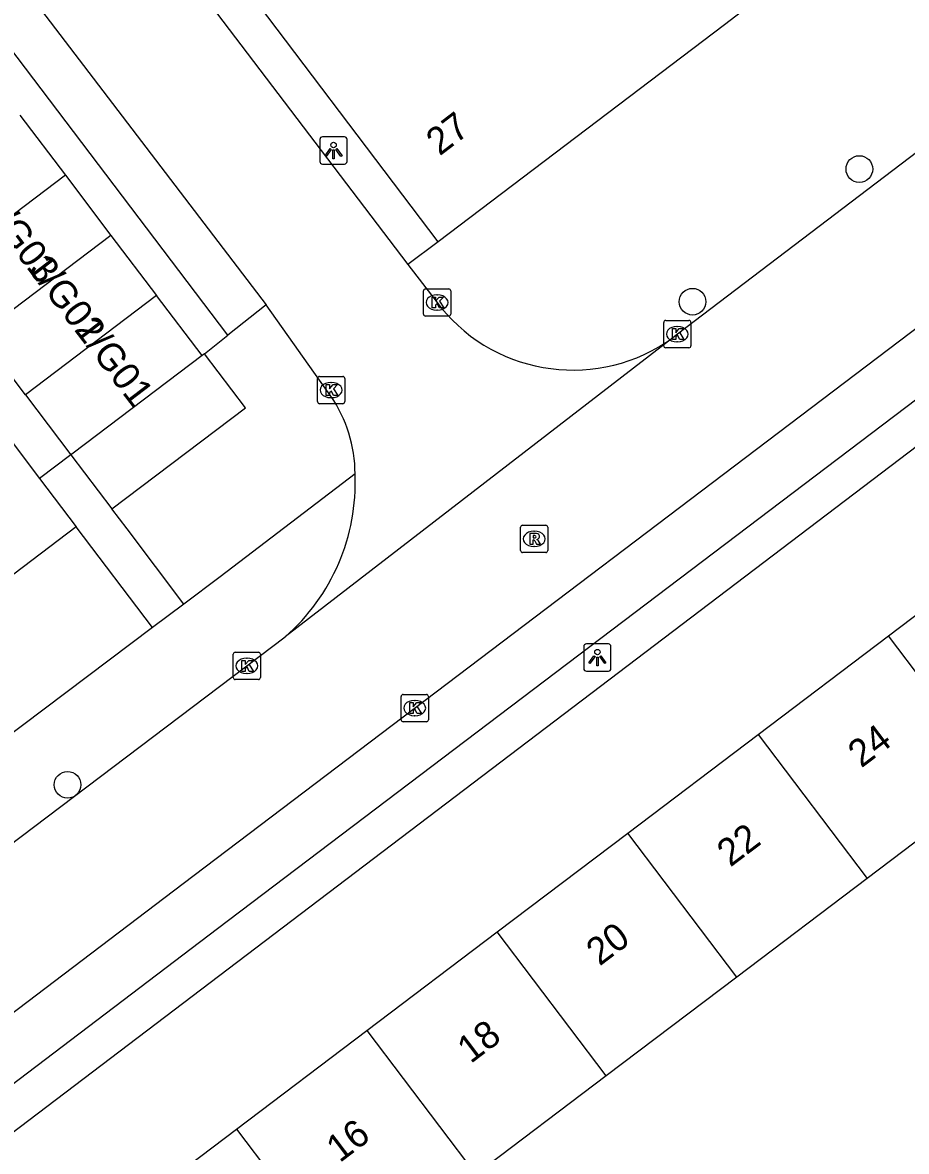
# Model space of a CAD drawing. Extents: x 160037 to 160839, y 385326 to 386441.
# Drawn here: x 160285.29 to 160317.7, y 385893.36 to 385934.78 of the extents above; entities that cross this region are included whole.
import ezdxf

# ---------------------------------------------------------------- set-up
doc = ezdxf.new("R2010")
doc.units = 0
for name, color, linetype in [('IMGEO_Boom', 7, 'Continuous'), ('IMGEO_Groenvoorziening', 7, 'Continuous'), ('IMGEO_Kolk', 7, 'Continuous'), ('IMGEO_Lage_trafo', 7, 'Continuous'), ('IMGEO_Lichtpunt', 7, 'Continuous'), ('IMGEO_Pand', 7, 'Continuous'), ('IMGEO_Pand_nummerreeks', 7, 'Continuous'), ('IMGEO_Rijbaan_lokaal_open', 7, 'Continuous'), ('IMGEO_Rioolput', 7, 'Continuous'), ('IMGEO_Voetpad_open', 7, 'Continuous')]:
    doc.layers.add(name, color=color, linetype=linetype)

msp = doc.modelspace()

# ---------------------------------------------------------------- linework, layer by layer
at = {"layer": 'IMGEO_Boom'}
for centre in [(160315.976, 385929.404), (160309.859, 385924.538), (160286.944, 385906.816)]:
    msp.add_circle(centre, 0.489, dxfattribs=at)
at = {"layer": 'IMGEO_Groenvoorziening'}
msp.add_lwpolyline([(160291.96, 385922.629), (160292.815, 385923.307)], dxfattribs=at)
at = {"layer": 'IMGEO_Kolk'}
for p, q in [((160299.993, 385924.082), (160299.993, 385924.934)), ((160300.068, 385925.008), (160300.92, 385925.008)), ((160300.481, 385924.788), (160300.506, 385924.788)), ((160300.994, 385924.934), (160300.994, 385924.082)), ((160300.92, 385924.008), (160300.068, 385924.008)), ((160300.504, 385924.228), (160300.479, 385924.228)), ((160308.801, 385922.923), (160308.801, 385923.775)), ((160308.876, 385923.849), (160309.728, 385923.849)), ((160309.289, 385923.629), (160309.314, 385923.629)), ((160309.802, 385923.775), (160309.802, 385922.923)), ((160309.728, 385922.849), (160308.876, 385922.849)), ((160309.312, 385923.069), (160309.287, 385923.069)), ((160296.107, 385920.871), (160296.107, 385921.723)), ((160296.182, 385921.797), (160297.034, 385921.797)), ((160296.595, 385921.577), (160296.62, 385921.577)), ((160297.108, 385921.723), (160297.108, 385920.871)), ((160297.034, 385920.797), (160296.182, 385920.797)), ((160296.618, 385921.017), (160296.593, 385921.017)), ((160293.015, 385910.751), (160293.015, 385911.603)), ((160293.09, 385911.677), (160293.942, 385911.677)), ((160294.016, 385911.603), (160294.016, 385910.751)), ((160293.503, 385911.457), (160293.528, 385911.457)), ((160293.942, 385910.677), (160293.09, 385910.677)), ((160293.526, 385910.897), (160293.501, 385910.897)), ((160299.172, 385909.204), (160299.172, 385910.056)), ((160299.247, 385910.13), (160300.099, 385910.13)), ((160299.66, 385909.91), (160299.685, 385909.91)), ((160300.173, 385910.056), (160300.173, 385909.204)), ((160300.099, 385909.13), (160299.247, 385909.13)), ((160299.683, 385909.35), (160299.658, 385909.35))]:
    msp.add_line(p, q, dxfattribs=at)
for points in [[(160299.993, 385924.082), (160299.993, 385924.934)], [(160300.068, 385925.008), (160300.92, 385925.008)], [(160300.994, 385924.934), (160300.994, 385924.082)], [(160300.314, 385924.708), (160300.437, 385924.708), (160300.437, 385924.557), (160300.567, 385924.708), (160300.731, 385924.708), (160300.585, 385924.557), (160300.738, 385924.308), (160300.586, 385924.308), (160300.501, 385924.472), (160300.437, 385924.405), (160300.437, 385924.308), (160300.314, 385924.308), (160300.314, 385924.708)], [(160300.92, 385924.008), (160300.068, 385924.008)], [(160308.801, 385922.923), (160308.801, 385923.775)], [(160308.876, 385923.849), (160309.728, 385923.849)], [(160309.122, 385923.549), (160309.245, 385923.549), (160309.245, 385923.398), (160309.375, 385923.549), (160309.539, 385923.549), (160309.393, 385923.398), (160309.546, 385923.149), (160309.394, 385923.149), (160309.309, 385923.313), (160309.245, 385923.246), (160309.245, 385923.149), (160309.122, 385923.149), (160309.122, 385923.549)], [(160309.802, 385923.775), (160309.802, 385922.923)], [(160309.728, 385922.849), (160308.876, 385922.849)], [(160296.107, 385920.871), (160296.107, 385921.723)], [(160296.182, 385921.797), (160297.034, 385921.797)], [(160296.428, 385921.497), (160296.551, 385921.497), (160296.551, 385921.346), (160296.681, 385921.497), (160296.845, 385921.497), (160296.699, 385921.346), (160296.852, 385921.097), (160296.7, 385921.097), (160296.615, 385921.261), (160296.551, 385921.194), (160296.551, 385921.097), (160296.428, 385921.097), (160296.428, 385921.497)], [(160297.108, 385921.723), (160297.108, 385920.871)], [(160297.034, 385920.797), (160296.182, 385920.797)], [(160293.015, 385910.751), (160293.015, 385911.603)], [(160293.09, 385911.677), (160293.942, 385911.677)], [(160294.016, 385911.603), (160294.016, 385910.751)], [(160293.336, 385911.377), (160293.459, 385911.377), (160293.459, 385911.226), (160293.589, 385911.377), (160293.753, 385911.377), (160293.607, 385911.226), (160293.76, 385910.977), (160293.608, 385910.977), (160293.523, 385911.141), (160293.459, 385911.074), (160293.459, 385910.977), (160293.336, 385910.977), (160293.336, 385911.377)], [(160293.942, 385910.677), (160293.09, 385910.677)], [(160299.172, 385909.204), (160299.172, 385910.056)], [(160299.247, 385910.13), (160300.099, 385910.13)], [(160300.173, 385910.056), (160300.173, 385909.204)], [(160299.493, 385909.83), (160299.616, 385909.83), (160299.616, 385909.679), (160299.746, 385909.83), (160299.91, 385909.83), (160299.764, 385909.679), (160299.917, 385909.43), (160299.765, 385909.43), (160299.68, 385909.594), (160299.616, 385909.527), (160299.616, 385909.43), (160299.493, 385909.43), (160299.493, 385909.83)], [(160300.099, 385909.13), (160299.247, 385909.13)]]:
    msp.add_lwpolyline(points, dxfattribs=at)
for centre, start, end in [((160300.07, 385924.932), 91.552, 178.448), ((160300.07, 385924.932), 91.552, 178.448), ((160300.918, 385924.932), 1.552, 88.448), ((160300.918, 385924.932), 1.552, 88.448), ((160300.07, 385924.084), 181.552, 268.448), ((160300.07, 385924.084), 181.552, 268.448), ((160300.918, 385924.084), 271.552, 358.448), ((160300.918, 385924.084), 271.552, 358.448), ((160308.878, 385923.773), 91.552, 178.448), ((160308.878, 385923.773), 91.552, 178.448), ((160309.726, 385923.773), 1.552, 88.448), ((160309.726, 385923.773), 1.552, 88.448), ((160308.878, 385922.925), 181.552, 268.448), ((160308.878, 385922.925), 181.552, 268.448), ((160309.726, 385922.925), 271.552, 358.448), ((160309.726, 385922.925), 271.552, 358.448), ((160296.184, 385921.721), 91.552, 178.448), ((160296.184, 385921.721), 91.552, 178.448), ((160297.032, 385921.721), 1.552, 88.448), ((160297.032, 385921.721), 1.552, 88.448), ((160296.184, 385920.873), 181.552, 268.448), ((160296.184, 385920.873), 181.552, 268.448), ((160297.032, 385920.873), 271.552, 358.448), ((160297.032, 385920.873), 271.552, 358.448), ((160293.092, 385911.601), 91.552, 178.448), ((160293.092, 385911.601), 91.552, 178.448), ((160293.94, 385911.601), 1.552, 88.448), ((160293.94, 385911.601), 1.552, 88.448), ((160293.092, 385910.753), 181.552, 268.448), ((160293.092, 385910.753), 181.552, 268.448), ((160293.94, 385910.753), 271.552, 358.448), ((160293.94, 385910.753), 271.552, 358.448), ((160299.249, 385910.054), 91.552, 178.448), ((160299.249, 385910.054), 91.552, 178.448), ((160300.097, 385910.054), 1.552, 88.448), ((160300.097, 385910.054), 1.552, 88.448), ((160299.249, 385909.206), 181.552, 268.448), ((160299.249, 385909.206), 181.552, 268.448), ((160300.097, 385909.206), 271.552, 358.448), ((160300.097, 385909.206), 271.552, 358.448)]:
    msp.add_arc(centre, 0.0765, start, end, dxfattribs=at)
for centre, major_axis, ratio, start_param, end_param in [((160300.48, 385924.508), (-0.387, 0.002), 0.722429, 4.712389, 7.853982), ((160300.505, 385924.508), (-0.39, 0.002), 0.717154, 1.570796, 4.712389), ((160309.288, 385923.349), (-0.387, 0.002), 0.722429, 4.712389, 7.853982), ((160309.313, 385923.349), (-0.39, 0.002), 0.717154, 1.570796, 4.712389), ((160296.594, 385921.297), (-0.387, 0.002), 0.722429, 4.712389, 7.853982), ((160296.619, 385921.297), (-0.39, 0.002), 0.717154, 1.570796, 4.712389), ((160293.502, 385911.177), (-0.387, 0.002), 0.722429, 4.712389, 7.853982), ((160293.527, 385911.177), (-0.39, 0.002), 0.717154, 1.570796, 4.712389), ((160299.659, 385909.63), (-0.387, 0.002), 0.722429, 4.712389, 7.853982), ((160299.684, 385909.63), (-0.39, 0.002), 0.717154, 1.570796, 4.712389)]:
    msp.add_ellipse(centre, major_axis=major_axis, ratio=ratio, start_param=start_param, end_param=end_param, dxfattribs=at)
at = {"layer": 'IMGEO_Lage_trafo'}
for points in [[(160288.567, 385916.938), (160293.467, 385920.64), (160291.96, 385922.629)], [(160291.96, 385922.629), (160291.873, 385922.56)], [(160287.066, 385918.921), (160288.567, 385916.938)]]:
    msp.add_lwpolyline(points, dxfattribs=at)
at = {"layer": 'IMGEO_Lichtpunt'}
for p, q in [((160297.098, 385930.584), (160296.29, 385930.584)), ((160297.098, 385930.584), (160296.29, 385930.584)), ((160296.196, 385930.489), (160296.196, 385929.682)), ((160296.196, 385930.489), (160296.196, 385929.682)), ((160297.192, 385929.682), (160297.192, 385930.489)), ((160297.192, 385929.682), (160297.192, 385930.489)), ((160296.29, 385929.588), (160297.098, 385929.588)), ((160296.29, 385929.588), (160297.098, 385929.588)), ((160306.774, 385911.982), (160305.966, 385911.982)), ((160306.774, 385911.982), (160305.966, 385911.982)), ((160305.872, 385911.887), (160305.872, 385911.08)), ((160305.872, 385911.887), (160305.872, 385911.08)), ((160306.868, 385911.08), (160306.868, 385911.887)), ((160306.868, 385911.08), (160306.868, 385911.887)), ((160305.966, 385910.986), (160306.774, 385910.986)), ((160305.966, 385910.986), (160306.774, 385910.986))]:
    msp.add_line(p, q, dxfattribs=at)
for points in [[(160296.57, 385930.153), (160296.609, 385930.125), (160296.421, 385929.863), (160296.383, 385929.89), (160296.57, 385930.153)], [(160296.782, 385930.125), (160296.82, 385930.152), (160297.007, 385929.89), (160296.968, 385929.862), (160296.782, 385930.125)], [(160296.672, 385930.105), (160296.719, 385930.105), (160296.719, 385929.783), (160296.672, 385929.783), (160296.672, 385930.105)], [(160306.246, 385911.551), (160306.285, 385911.523), (160306.097, 385911.261), (160306.059, 385911.288), (160306.246, 385911.551)], [(160306.348, 385911.503), (160306.395, 385911.503), (160306.395, 385911.181), (160306.348, 385911.181), (160306.348, 385911.503)], [(160306.458, 385911.523), (160306.496, 385911.55), (160306.683, 385911.288), (160306.644, 385911.26), (160306.458, 385911.523)]]:
    msp.add_lwpolyline(points, dxfattribs=at)
for centre in [(160296.695, 385930.287), (160306.371, 385911.685)]:
    msp.add_circle(centre, 0.0994, dxfattribs=at)
for centre, start, end in [((160296.29, 385930.489), 90, 180), ((160296.29, 385930.489), 90, 180), ((160297.098, 385930.489), 0, 90), ((160297.098, 385930.489), 0, 90), ((160296.29, 385929.682), 180, 270), ((160296.29, 385929.682), 180, 270), ((160297.098, 385929.682), 270, 0), ((160297.098, 385929.682), 270, 360), ((160305.966, 385911.887), 90, 180), ((160305.966, 385911.887), 90, 180), ((160306.774, 385911.887), 0, 90), ((160306.774, 385911.887), 0, 90), ((160305.966, 385911.08), 180, 270), ((160305.966, 385911.08), 180, 270), ((160306.774, 385911.08), 270, 0), ((160306.774, 385911.08), 270, 360)]:
    msp.add_arc(centre, 0.0946, start, end, dxfattribs=at)
at = {"layer": 'IMGEO_Pand'}
for points in [[(160300.528, 385926.728), (160274.238, 385961.479), (160273.026, 385963.07)], [(160315.959, 385938.476), (160311.028, 385934.695), (160300.528, 385926.728)], [(160285.192, 385931.384), (160286.862, 385929.178)], [(160286.862, 385929.178), (160282.056, 385925.539)], [(160286.862, 385929.178), (160288.533, 385926.972)], [(160288.533, 385926.972), (160283.726, 385923.333)], [(160288.533, 385926.972), (160290.203, 385924.766)], [(160290.203, 385924.766), (160285.396, 385921.127)], [(160291.873, 385922.56), (160290.203, 385924.766)], [(160285.396, 385921.127), (160283.726, 385923.333)], [(160291.873, 385922.56), (160287.149, 385918.984), (160287.066, 385918.921)], [(160283.21, 385921.624), (160284.24, 385920.265), (160285.917, 385918.052)], [(160285.396, 385921.127), (160287.066, 385918.921)], [(160285.917, 385918.052), (160287.26, 385916.28)], [(160287.26, 385916.28), (160282.366, 385912.571)], [(160317.045, 385912.28), (160321.827, 385915.9)], [(160312.263, 385908.659), (160317.045, 385912.28)], [(160321.042, 385907), (160317.045, 385912.28)], [(160307.481, 385905.039), (160312.263, 385908.659)], [(160312.263, 385908.659), (160316.26, 385903.38)], [(160321.042, 385907), (160316.26, 385903.38)], [(160302.699, 385901.418), (160307.481, 385905.039)], [(160311.478, 385899.76), (160307.481, 385905.039)], [(160316.26, 385903.38), (160311.478, 385899.76)], [(160297.918, 385897.798), (160302.699, 385901.418)], [(160306.696, 385896.139), (160302.699, 385901.418)], [(160311.478, 385899.76), (160306.696, 385896.139)], [(160293.136, 385894.177), (160297.918, 385897.798)], [(160297.918, 385897.798), (160301.914, 385892.519)], [(160306.696, 385896.139), (160301.914, 385892.519)], [(160288.353, 385890.556), (160293.136, 385894.177)], [(160293.136, 385894.177), (160297.132, 385888.898)]]:
    msp.add_lwpolyline(points, dxfattribs=at)
at = {"layer": 'IMGEO_Rijbaan_lokaal_open'}
for points in [[(160271.801, 385962.176), (160272.271, 385961.56), (160274.289, 385958.969), (160299.426, 385925.902)], [(160272.504, 385952.949), (160278.21, 385945.409), (160294.227, 385924.426)], [(160321.054, 385932.279), (160320.872, 385932.139), (160309.303, 385923.348), (160309.139, 385923.215)], [(160259.707, 385879.286), (160260.226, 385879.69), (160291.178, 385903.192), (160322.288, 385926.767)], [(160300.528, 385926.728), (160299.426, 385925.902)], [(160299.426, 385925.902), (160300.493, 385924.507), (160300.632, 385924.328)], [(160296.595, 385921.073), (160294.227, 385924.426)], [(160309.139, 385923.215), (160294.924, 385912.241)], [(160226.524, 385860.463), (160232.453, 385864.762), (160236.592, 385867.964), (160250.573, 385878.611), (160272.144, 385895.008), (160294.924, 385912.241)]]:
    msp.add_lwpolyline(points, dxfattribs=at)
for centre, radius, start, end in [((160305.475, 385928.281), 6.252, 219.2186, 305.8737), ((160292.466, 385918.22), 5.019, 0.0052, 34.6456), ((160289.966, 385917.903), 7.526, 311.2089, 2.417)]:
    msp.add_arc(centre, radius, start, end, dxfattribs=at)
at = {"layer": 'IMGEO_Rioolput'}
for p, q in [((160303.552, 385915.411), (160303.552, 385916.263)), ((160303.627, 385916.337), (160304.479, 385916.337)), ((160304.04, 385916.117), (160304.065, 385916.117)), ((160304.553, 385916.263), (160304.553, 385915.411)), ((160304.479, 385915.337), (160303.627, 385915.337)), ((160304.063, 385915.557), (160304.038, 385915.557))]:
    msp.add_line(p, q, dxfattribs=at)
for points in [[(160303.552, 385915.411), (160303.552, 385916.263)], [(160303.627, 385916.337), (160304.479, 385916.337)], [(160304.553, 385916.263), (160304.553, 385915.411)], [(160304.141, 385916.035), (160303.889, 385916.037), (160303.889, 385915.637)], [(160303.889, 385915.637), (160304.013, 385915.637), (160304.013, 385915.799), (160304.024, 385915.799)], [(160304.067, 385915.956), (160304.013, 385915.956), (160304.013, 385915.875)], [(160304.013, 385915.875), (160304.065, 385915.875)], [(160304.071, 385915.77), (160304.142, 385915.637), (160304.282, 385915.637), (160304.217, 385915.763)], [(160304.479, 385915.337), (160303.627, 385915.337)]]:
    msp.add_lwpolyline(points, dxfattribs=at)
for centre, radius, start, end in [((160303.629, 385916.261), 0.0765, 91.552, 178.448), ((160303.629, 385916.261), 0.0765, 91.552, 178.448), ((160304.477, 385916.261), 0.0765, 1.552, 88.448), ((160304.477, 385916.261), 0.0765, 1.552, 88.448), ((160304.023, 385915.746), 0.0533, 26.0293, 88.6989), ((160304.049, 385916.064), 0.19, 274.7715, 282.9687), ((160304.073, 385915.86), 0.0964, 77.0061, 93.1865), ((160304.087, 385915.917), 0.0378, 276.6634, 79.6772), ((160304.14, 385915.925), 0.109, 350.3612, 89.416), ((160304.138, 385915.925), 0.112, 277.5842, 350.9817), ((160304.122, 385915.71), 0.108, 29.5134, 73.7905), ((160303.629, 385915.413), 0.0765, 181.552, 268.448), ((160303.629, 385915.413), 0.0765, 181.552, 268.448), ((160304.477, 385915.413), 0.0765, 271.552, 358.448), ((160304.477, 385915.413), 0.0765, 271.552, 358.448)]:
    msp.add_arc(centre, radius, start, end, dxfattribs=at)
for centre, major_axis, ratio, start_param, end_param in [((160304.039, 385915.837), (-0.387, 0.002), 0.722429, 4.712389, 7.853982), ((160304.064, 385915.837), (-0.39, 0.002), 0.717154, 1.570796, 4.712389)]:
    msp.add_ellipse(centre, major_axis=major_axis, ratio=ratio, start_param=start_param, end_param=end_param, dxfattribs=at)
at = {"layer": 'IMGEO_Voetpad_open'}
for points in [[(160292.815, 385923.307), (160271.131, 385951.947)], [(160256.578, 385872.537), (160326.435, 385925.58)], [(160294.227, 385924.426), (160292.815, 385923.307)], [(160320.145, 385922.524), (160292.441, 385901.527), (160267.148, 385882.321), (160263.491, 385879.768)], [(160287.066, 385918.921), (160285.917, 385918.052)], [(160297.485, 385918.22), (160292.54, 385914.445), (160291.211, 385913.446)], [(160291.211, 385913.446), (160289.125, 385916.201), (160288.567, 385916.938)], [(160290.062, 385912.583), (160287.26, 385916.28)], [(160291.211, 385913.446), (160290.062, 385912.583)], [(160290.062, 385912.583), (160283.686, 385907.791), (160267.87, 385895.673), (160243.764, 385877.424), (160234.086, 385870.009), (160228.256, 385865.652), (160224.033, 385862.374)]]:
    msp.add_lwpolyline(points, dxfattribs=at)

# ---------------------------------------------------------------- texts
at = {"layer": 'IMGEO_Pand_nummerreeks'}
for s, rotation, p in [('27', 37.4772, (160300.586, 385929.864)), ('1/G03', 307.3301, (160283.719, 385928.024)), ('1/G02', 307.3301, (160285.402, 385925.817)), ('1/G01', 307.3301, (160287.16, 385923.513)), ('24', 37.1309, (160316.047, 385907.41)), ('22', 37.1309, (160311.245, 385903.775)), ('20', 37.1309, (160306.451, 385900.144)), ('18', 37.1309, (160301.723, 385896.565)), ('16', 37.1334, (160296.921, 385892.928))]:
    msp.add_text(s, height=1, rotation=rotation, dxfattribs=at).set_placement(p)

doc.saveas('drawing.dxf')
